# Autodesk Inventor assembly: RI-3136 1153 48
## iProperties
Shininess: 0.0
Length Units: 11269
Angle Units: 11279
Time Units: 11290
Mass Units: 11283
Length Display Precision: 3
Angle Display Precision: 2
Compacted: True
Created: 2000-11
Part Number: RI-3136 1153 48
Description: Left side cover
Document SubType Name: Assembly
Designer: Joe M
Engineer: Joe M
Density: 7.860000000000002
Volumn: 890.1989264859282
Area: 4643.093456685721
PropertySet Name: Model Information
Control State: 0
Master: False
Checked Out: False
Title: Sidoplåt vänster
Author: Joe M
